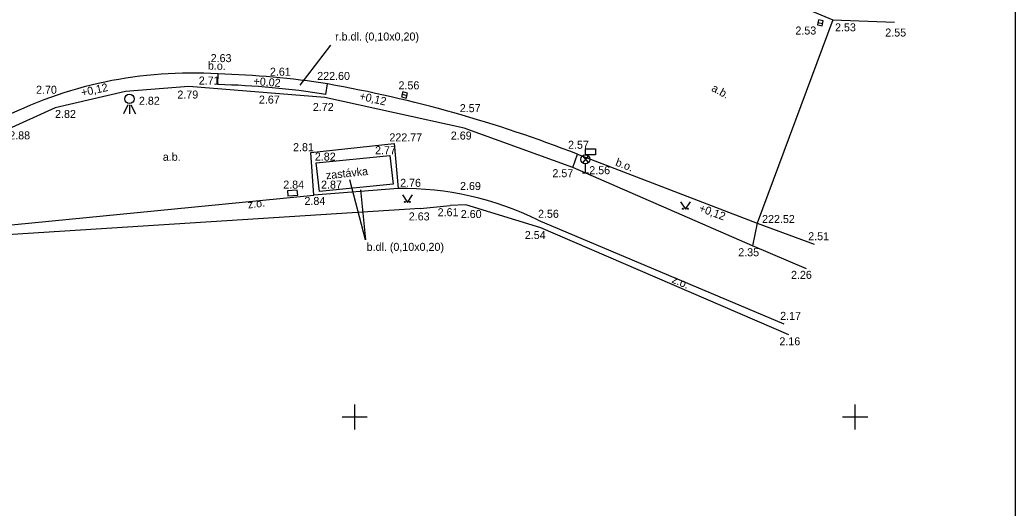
# Model space of a CAD drawing. Extents: x -598741 to -598592, y -1156973 to -1156763.
# Drawn here: x -598641.73 to -598592.01, y -1156904.55 to -1156880.16 of the extents above; entities that cross this region are included whole.
import ezdxf

# ---------------------------------------------------------------- set-up
doc = ezdxf.new("R2010")
doc.units = 0
for name, color, linetype in [('Vrstva 10', 7, 'Continuous'), ('Vrstva 13', 7, 'Continuous'), ('Vrstva 14', 7, 'Continuous'), ('Vrstva 19', 7, 'Continuous'), ('Vrstva 25', 7, 'Continuous'), ('Vrstva 29', 7, 'Continuous'), ('Vrstva 44', 7, 'Continuous'), ('Vrstva 49', 7, 'Continuous'), ('Vrstva 5', 7, 'Continuous'), ('Vrstva 50', 7, 'Continuous'), ('Vrstva 58', 7, 'Continuous'), ('Vrstva 61', 7, 'Continuous'), ('Vrstva 62', 7, 'Continuous'), ('Vrstva 63', 7, 'Continuous'), ('Vrstva 7', 7, 'Continuous')]:
    doc.layers.add(name, color=color, linetype=linetype)

msp = doc.modelspace()

# ---------------------------------------------------------------- linework, layer by layer
at = {"layer": 'Vrstva 10'}
for points in [[(-598603.32, -1156895.9), (-598615.71, -1156890.55), (-598619.46, -1156889.4), (-598620.23, -1156889.43)], [(-598621.74, -1156889.58), (-598642.9, -1156890.94), (-598644.87, -1156891.57), (-598666.18, -1156904.5), (-598682.28, -1156914.49), (-598689.54, -1156918.79), (-598690.41, -1156923.11), (-598688.22, -1156929.02)]]:
    msp.add_lwpolyline(points, dxfattribs=at)
at = {"layer": 'Vrstva 13'}
for centre, radius, start, end in [((-598673.908, -1156854.609), 34.374, 299.1499, 340.9676), ((-598673.875, -1156854.607), 36.879, 299.4847, 340.804)]:
    msp.add_arc(centre, radius, start, end, dxfattribs=at)
at = {"layer": 'Vrstva 14'}
for points in [[(-598622.62, -1156888.905), (-598622.37, -1156889.28), (-598622.12, -1156888.905)], [(-598608.73, -1156889.245), (-598608.48, -1156889.62), (-598608.23, -1156889.245)]]:
    msp.add_lwpolyline(points, dxfattribs=at)
for centre in [(-598622.495, -1156889.255), (-598622.245, -1156889.255), (-598608.605, -1156889.595), (-598608.355, -1156889.595)]:
    msp.add_circle(centre, 0.025, dxfattribs=at)
at = {"layer": 'Vrstva 19'}
msp.add_arc((-598673.891, -1156854.609), 35.626, 299.3215, 340.8845, dxfattribs=at)
at = {"layer": 'Vrstva 25'}
for p, q in [((-598601.863, -1156880.286), (-598601.617, -1156880.334)), ((-598622.641, -1156883.877), (-598622.399, -1156883.943))]:
    msp.add_line(p, q, dxfattribs=at)
for points in [[(-598601.887, -1156880.409), (-598601.642, -1156880.458), (-598601.593, -1156880.212), (-598601.838, -1156880.163)], [(-598622.674, -1156883.999), (-598622.432, -1156884.064), (-598622.367, -1156883.822), (-598622.608, -1156883.757)]]:
    msp.add_lwpolyline(points, close=True, dxfattribs=at)
at = {"layer": 'Vrstva 29'}
msp.add_lwpolyline([(-598627.872, -1156888.663), (-598628.37, -1156888.707), (-598628.348, -1156888.956), (-598627.85, -1156888.912)], close=True, dxfattribs=at)
at = {"layer": 'Vrstva 44'}
for p, q in [((-598636.334, -1156884.403), (-598636.56, -1156884.855)), ((-598636.26, -1156884.405), (-598636.26, -1156884.855)), ((-598636.185, -1156884.403), (-598635.96, -1156884.855)), ((-598613.33, -1156886.96), (-598613.63, -1156887.304)), ((-598613.63, -1156886.96), (-598613.33, -1156887.304)), ((-598613.48, -1156887.81), (-598613.48, -1156887.36)), ((-598613.63, -1156887.81), (-598613.33, -1156887.81))]:
    msp.add_line(p, q, dxfattribs=at)
msp.add_lwpolyline([(-598613.48, -1156886.604), (-598612.98, -1156886.604), (-598612.98, -1156886.904), (-598613.48, -1156886.904)], close=True, dxfattribs=at)
for centre, radius in [((-598636.26, -1156884.11), 0.234), ((-598613.48, -1156887.132), 0.228)]:
    msp.add_circle(centre, radius, dxfattribs=at)
at = {"layer": 'Vrstva 49'}
msp.add_line((-598626.21, -1156881.43), (-598627.75, -1156883.42), dxfattribs=at)
msp.add_lwpolyline([(-598624.711, -1156888.644), (-598624.46, -1156891.15), (-598625.25, -1156888.15)], dxfattribs=at)
at = {"layer": 'Vrstva 5'}
msp.add_line((-598621.74, -1156889.58), (-598620.23, -1156889.43), dxfattribs=at)
at = {"layer": 'Vrstva 61'}
msp.add_lwpolyline([(-598740.51, -1156762.629), (-598592.01, -1156762.63), (-598592.01, -1156972.63), (-598740.511, -1156972.63)], close=True, dxfattribs=at)
at = {"layer": 'Vrstva 62'}
for p, q in [((-598625, -1156900.625), (-598625, -1156899.375)), ((-598600, -1156900.625), (-598600, -1156899.375)), ((-598625.625, -1156900), (-598624.375, -1156900)), ((-598600.625, -1156900), (-598599.375, -1156900))]:
    msp.add_line(p, q, dxfattribs=at)
at = {"layer": 'Vrstva 63'}
msp.add_lwpolyline([(-598604.71, -1156878.64), (-598601.11, -1156880.16), (-598604.9, -1156890.31), (-598605.13, -1156891.45), (-598614.1, -1156887.53), (-598619.54, -1156885.57), (-598626.5, -1156884.03), (-598633.29, -1156883.49), (-598636.46, -1156883.74), (-598639.97, -1156884.56), (-598642.51, -1156885.7)], dxfattribs=at)
at = {"layer": 'Vrstva 7'}
for p, q in [((-598601.11, -1156880.16), (-598598.03, -1156880.28)), ((-598631.84, -1156883.39), (-598631.83, -1156882.86)), ((-598626.45, -1156883.88), (-598626.36, -1156883.36)), ((-598642.86, -1156890.46), (-598627.05, -1156888.92)), ((-598615.84, -1156890.16), (-598603.57, -1156895.34))]:
    msp.add_line(p, q, dxfattribs=at)
msp.add_lwpolyline([(-598627.05, -1156888.92), (-598627.2, -1156886.79), (-598623.03, -1156886.34), (-598622.83, -1156888.59)], close=True, dxfattribs=at)
for points in [[(-598626.77, -1156888.74), (-598626.93, -1156887.3), (-598623.25, -1156886.93), (-598623.09, -1156888.37), (-598626.77, -1156888.74)], [(-598602.44, -1156892.6), (-598605.13, -1156891.45), (-598614.1, -1156887.53), (-598613.88, -1156886.87)], [(-598613.88, -1156886.87), (-598604.9, -1156890.31), (-598602.05, -1156891.37)]]:
    msp.add_lwpolyline(points, dxfattribs=at)
for centre, radius, start, end in [((-598633.185, -1156903.631), 20.815, 86.2673, 117.5731), ((-598632.941, -1156925.183), 42.337, 81.0579, 88.4966), ((-598632.915, -1156925.11), 41.733, 81.0877, 88.5234), ((-598637.775, -1156947.888), 65.529, 68.61444, 79.96829), ((-598622.638, -1156904.082), 15.494, 63.9735, 90.7086)]:
    msp.add_arc(centre, radius, start, end, dxfattribs=at)

# ---------------------------------------------------------------- texts
at = {"layer": 'Vrstva 49'}
for s, p in [('r.b.dl. (0,10x0,20)', (-598625.985, -1156881.19)), ('a.b.', (-598634.593, -1156887.2)), ('b.dl. (0,10x0,20)', (-598624.41, -1156891.7))]:
    msp.add_text(s, height=0.4, dxfattribs=at).set_placement(p)
for s, rotation, p in [('b.o.', 358.6424, (-598632.344, -1156882.641)), ('a.b.', 331.46, (-598607.215, -1156883.686)), ('b.o.', 339.1836, (-598612.011, -1156887.428)), ('zastávka', 5.9585, (-598626.423, -1156888.127)), ('z.o.', 6.8673, (-598630.326, -1156889.588)), ('z.o.', 337.3302, (-598609.194, -1156893.273))]:
    msp.add_text(s, height=0.4, rotation=rotation, dxfattribs=at).set_placement(p)
at = {"layer": 'Vrstva 50'}
for s, rotation, p in [('+0,02', 355.6934, (-598630.072, -1156883.411)), ('+0,12', 12.3886, (-598638.627, -1156883.994)), ('+0,12', 347.0644, (-598624.799, -1156884.139)), ('+0,12', 339.6996, (-598607.842, -1156889.718))]:
    msp.add_text(s, height=0.4, rotation=rotation, dxfattribs=at).set_placement(p)
at = {"layer": 'Vrstva 58'}
for s, p in [('2.53', (-598602.986, -1156880.89)), ('2.53', (-598601.006, -1156880.73)), ('2.55', (-598598.496, -1156880.99)), ('2.63', (-598632.203, -1156882.27)), ('2.61', (-598629.242, -1156882.95)), ('2.71', (-598632.796, -1156883.39)), ('222.60', (-598626.878, -1156883.16)), ('2.70', (-598640.926, -1156883.85)), ('2.56', (-598622.816, -1156883.63)), ('2.82', (-598635.786, -1156884.4)), ('2.79', (-598633.866, -1156884.09)), ('2.67', (-598629.792, -1156884.342)), ('2.72', (-598627.096, -1156884.71)), ('2.57', (-598619.756, -1156884.77)), ('2.82', (-598639.976, -1156885.06)), ('2.88', (-598642.266, -1156886.13)), ('222.77', (-598623.272, -1156886.23)), ('2.69', (-598620.203, -1156886.14)), ('2.81', (-598628.086, -1156886.72)), ('2.77', (-598623.986, -1156886.87)), ('2.57', (-598614.346, -1156886.6)), ('2.82', (-598626.996, -1156887.19)), ('2.56', (-598613.286, -1156887.87)), ('2.57', (-598615.126, -1156888.02)), ('2.84', (-598628.576, -1156888.59)), ('2.87', (-598626.686, -1156888.59)), ('2.76', (-598622.736, -1156888.5)), ('2.69', (-598619.743, -1156888.66)), ('2.84', (-598627.516, -1156889.408)), ('2.61', (-598620.862, -1156889.97)), ('2.63', (-598622.303, -1156890.18)), ('2.60', (-598619.706, -1156890.06)), ('2.56', (-598615.846, -1156890.05)), ('222.52', (-598604.652, -1156890.31)), ('2.54', (-598616.506, -1156891.11)), ('2.51', (-598602.346, -1156891.17)), ('2.35', (-598605.842, -1156891.97)), ('2.26', (-598603.206, -1156893.1)), ('2.17', (-598603.746, -1156895.15)), ('2.16', (-598603.786, -1156896.42))]:
    msp.add_text(s, height=0.4, dxfattribs=at).set_placement(p)

doc.saveas('drawing.dxf')
